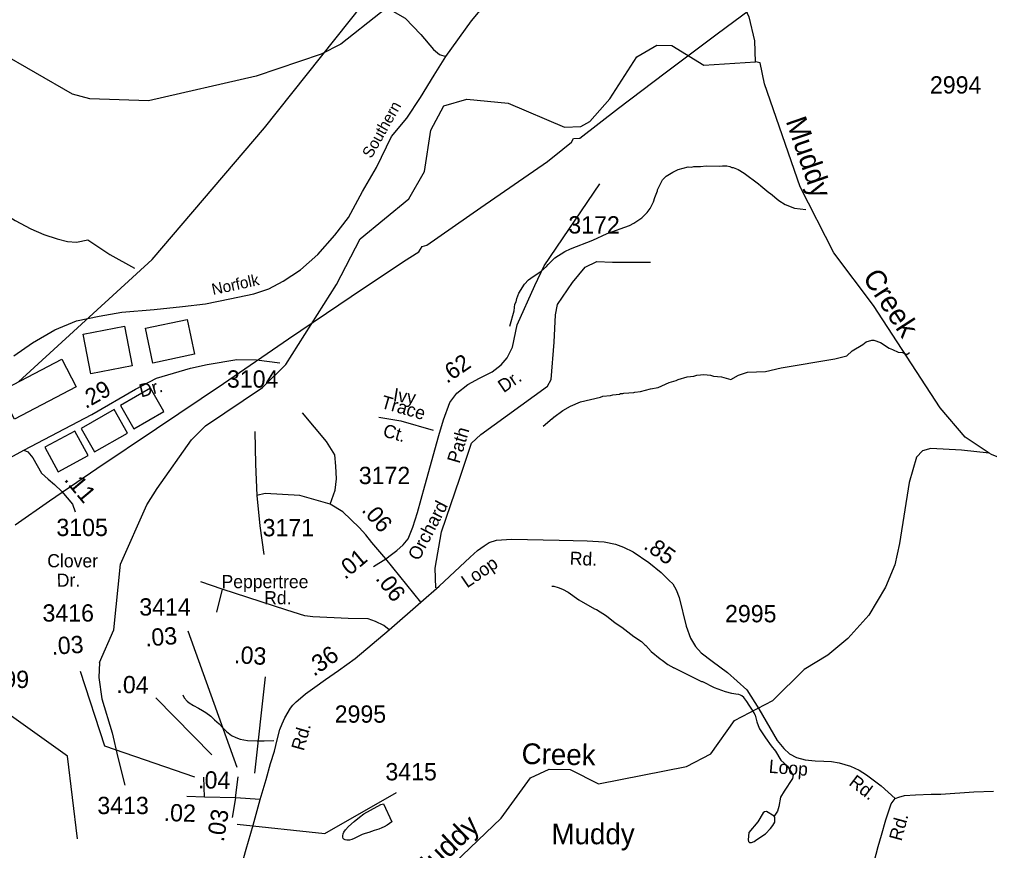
# Model space of a CAD drawing. Extents: x 1547597 to 1699558, y 810033 to 920809.
# Drawn here: x 1595166 to 1602180, y 820357 to 826362 of the extents above; entities that cross this region are included whole.
import ezdxf

# ---------------------------------------------------------------- set-up
doc = ezdxf.new("R2010")
doc.units = 0
for name, color, linetype in [('Exist Boundary Political City Limit New', 7, 'Continuous'), ('Exist Cultural Church with Cemetery Label', 7, 'Continuous'), ('Exist Cultural Warehouse Building Footprint', 7, 'Continuous'), ('Exist Hydrographic Creek Single Shore', 7, 'Continuous'), ('Exist Hydrographic Misc Water Feature', 7, 'Continuous'), ('Exist Railroad Mainline', 7, 'Continuous'), ('Exist Railroad Mainline Label', 7, 'Continuous'), ('Exist Road Non-System Type 51', 7, 'Continuous'), ('Exist Road Non-System Type 51 Label', 7, 'Continuous'), ('Exist Road Secondary Mileage Hundredths English Label', 7, 'Continuous'), ('Exist Road Secondary Type 51 Attributed', 7, 'Continuous'), ('Exist Road Secondary Type 51 Label', 7, 'Continuous'), ('Exist Road Secondary Type 51 Number Label', 7, 'Continuous'), ('Exist Utilities Electrical Transmission Line', 7, 'Continuous'), ('Map Preparation Boundary City Limit Buffer Line', 7, 'Continuous'), ('Old_Level_32', 7, 'Continuous')]:
    doc.layers.add(name, color=color, linetype=linetype)

msp = doc.modelspace()

# ---------------------------------------------------------------- linework, layer by layer
at = {"layer": 'Exist Boundary Political City Limit New'}
msp.add_lwpolyline([(1595159.9, 823742.9), (1596126.5, 824626.4), (1596938.9, 825577.9), (1598671.6, 827755.3), (1599119.8, 828312.6), (1599862.2, 829685.3), (1600674.7, 831289.2), (1600128.4, 831887.3), (1599217.9, 832804.7), (1599067.4, 833015.2), (1598754.8, 833517.5), (1598535.5, 834121.7), (1598377.2, 834572.6), (1598149, 835207), (1597793.5, 835631), (1597451.9, 835864.5), (1596684.8, 836157), (1596268.5, 836512.2)], dxfattribs=at)
at = {"layer": 'Exist Cultural Warehouse Building Footprint'}
for points in [[(1595981.8, 823858.6), (1595682.6, 823800.3), (1595626.8, 824086.9), (1595926, 824145.1)], [(1596433.1, 823943), (1596131, 823879.6), (1596078.2, 824131.8), (1596380.2, 824195.2)], [(1595577.9, 823708.2), (1595130.7, 823474.8), (1595026.3, 823674.8), (1595473.5, 823908.2)], [(1596114.2, 823697.9), (1595896.6, 823573.4), (1595993.1, 823404.7), (1596210.7, 823529.1)], [(1595852.2, 823542.8), (1595612.8, 823407.2), (1595708.5, 823238.3), (1595947.9, 823374)], [(1595567.7, 823387.7), (1595351.3, 823270.9), (1595446.5, 823094.5), (1595662.9, 823211.4)]]:
    msp.add_lwpolyline(points, close=True, dxfattribs=at)
at = {"layer": 'Exist Hydrographic Creek Single Shore'}
for points in [[(1599148.6, 827468.1), (1599130.7, 827383.1), (1598893.6, 827085.9), (1598450.6, 827019.4), (1598373, 826911), (1597968.6, 826558.9), (1597775.8, 826410), (1597490.3, 826184.3), (1597347.3, 826111.7), (1596877.3, 825951.8), (1596099.6, 825773.7), (1595674.6, 825788.9), (1595550.7, 825820.9), (1595012.6, 826130.5), (1594738.6, 826218.2), (1594623.6, 826351.8), (1594518.6, 826587), (1594430.6, 826880.9), (1594384.6, 827203.6), (1594403.6, 827380.4), (1594498.6, 827654.3), (1594492.6, 827828.4), (1594348.6, 828264.6)], [(1600488.6, 826055.7), (1600482.7, 826206.8), (1600442.6, 826381.6), (1600353.6, 826550.8), (1600172.6, 826761.3), (1599545.6, 827253.3), (1599373.6, 827457), (1599331.6, 827474.3)], [(1595746.6, 821716.9), (1595849.6, 821951.2), (1595897.6, 822426.2), (1596086.7, 822855.7), (1596162.6, 822972.3), (1596409.6, 823325.1), (1596510.6, 823424.8), (1596922.7, 823702.1), (1597091.6, 823869.3), (1597457.6, 824446.2), (1597628.7, 824777.6), (1597982.6, 825065.9), (1598093.6, 825263.8), (1598139.6, 825561.6), (1598233.7, 825737), (1598401.6, 825786.1), (1598700.7, 825757), (1599106.7, 825584.7), (1599223.7, 825589), (1599290.6, 825623.7), (1599434.6, 825788.2), (1599630.7, 826092.8), (1599773.6, 826175.2), (1599881.7, 826173), (1600113.7, 826030.5), (1600488.6, 826055.7)], [(1602177, 823228.8), (1602003.6, 823343.1), (1601822.7, 823556.8), (1601340.6, 824295.3), (1601053.6, 824675.3), (1600810.7, 825153), (1600553.6, 825896.8), (1600521.6, 826048.5), (1600488.6, 826055.7)], [(1602177, 823228.8), (1601976.8, 823249.3), (1601755.2, 823260.9), (1601695.1, 823245.9), (1601652.4, 823198.6), (1601597.5, 823017.2), (1601528.2, 822576), (1601493.7, 822420.3), (1601427.1, 822259.3), (1601307.9, 822059), (1601155.2, 821889.4), (1601009.6, 821769.7), (1600839.8, 821665)], [(1603082.6, 822996.2), (1602433.6, 823120.9), (1602193.6, 823217.8), (1602177, 823228.8)], [(1595746.6, 821716.9), (1595740.5, 821606.9), (1595763.4, 821453.1), (1595837.8, 821207.4), (1595878.8, 821030.6), (1595929.5, 820829.6)], [(1597762.7, 819736), (1597806.6, 819853.3), (1597907.6, 819959.6), (1598142.6, 820105.9), (1598649.6, 820591.2), (1598861.6, 820882.3), (1598995.6, 820945.3), (1599146.7, 820942.2), (1599353.7, 820839.6), (1599988.6, 820964.6), (1600164.6, 821056.2), (1600334.6, 821295.7), (1600611.6, 821441.1), (1600839.8, 821665)]]:
    msp.add_lwpolyline(points, dxfattribs=at)
at = {"layer": 'Exist Hydrographic Misc Water Feature'}
for points in [[(1598712.7, 824146.2), (1598742.2, 824257.7), (1598748.9, 824305.6), (1598757.1, 824321.5), (1598761.4, 824345.4), (1598775.9, 824383.2), (1598818.8, 824448.6), (1598847.2, 824480.2), (1598879.5, 824505.7), (1598936, 824540.9), (1598976.5, 824576.4), (1598988.7, 824592.2), (1599037.3, 824639.5), (1599109.8, 824684.5), (1599150, 824703.9), (1599310.8, 824767.7), (1599415.5, 824816.2), (1599576.1, 824873.9), (1599608.3, 824889.5), (1599664.8, 824928.7), (1599703.4, 824968.2), (1599725.7, 824995.8), (1599750.3, 825043.5), (1599758.7, 825075.3), (1599779.4, 825123), (1599779.5, 825131), (1599814.5, 825202.5), (1599840.9, 825230.2), (1599889.1, 825259.5), (1599929.4, 825278.9), (1600001.6, 825295.9), (1600025.6, 825295.6), (1600041.6, 825299.4), (1600089.6, 825298.7), (1600129.7, 825304.1), (1600225.5, 825300.8), (1600249.6, 825304.4), (1600279.6, 825304), (1600301.5, 825299.7), (1600317.4, 825291.5), (1600325.4, 825291.4), (1600361.2, 825276.9), (1600404.8, 825252.3), (1600509.6, 825174.8), (1600525.4, 825158.6), (1600582.7, 825111.8), (1600596.7, 825103.6), (1600655.9, 825052.8), (1600701.6, 825024.2), (1600769.1, 824997.3), (1600851, 824987.8)], [(1601186.3, 823968.7), (1601263.4, 824014.6), (1601287.6, 824032.3), (1601327.8, 824045.7), (1601343.8, 824045.5), (1601391.6, 824028.8), (1601454.9, 823986), (1601478.8, 823977.6), (1601518.5, 823957.1), (1601550.4, 823954.6), (1601582.3, 823942.2), (1601599.7, 823954.9)], [(1600241.5, 823780.5), (1600310.2, 823760.6), (1600363.9, 823791.3), (1600429.9, 823812.5), (1600559, 823819.5), (1600672.7, 823843.8), (1601061.9, 823910.3), (1601147.2, 823932.1), (1601186.3, 823968.7)], [(1598952.7, 823423), (1599017.4, 823478), (1599023.4, 823479.9), (1599029.6, 823487.9), (1599094.2, 823536.9), (1599150.6, 823568.2), (1599222.9, 823599.2), (1599367.3, 823633.1), (1599383.4, 823640.9), (1599439.5, 823644.1), (1599455.5, 823649.9), (1599503.5, 823655.2), (1599511.5, 823659.1), (1599527.5, 823658.9), (1599535.6, 823662.8), (1599607.6, 823665.8), (1599615.7, 823669.7), (1599655.7, 823673.1), (1599728, 823694.1), (1599784.1, 823703.3), (1599864.4, 823738.2), (1599913, 823753.6), (1599928.7, 823761.3), (1599993, 823780.4), (1600041, 823783.7), (1600063, 823791.4), (1600089.1, 823795.1), (1600113.1, 823796.7), (1600161, 823792), (1600184.9, 823785.7), (1600241.5, 823780.5)], [(1599015.5, 822266.3), (1599028.9, 822266.2), (1599060.7, 822257.7), (1599092.5, 822245.3), (1599132.3, 822224.7), (1599211.5, 822167.7), (1599322.5, 822104.1), (1599338.4, 822097.9), (1599409.7, 822052.9), (1599473, 822002), (1599520.6, 821971.4), (1599607.6, 821904.2), (1599663.1, 821867.4), (1599686.8, 821843.1), (1599694.7, 821839), (1599732.1, 821796.5), (1599797.3, 821741.6), (1599813.2, 821733.4), (1599852.6, 821700.8), (1599897.7, 821677.5)], [(1600484.2, 821336), (1600476.9, 821351.8), (1600461.9, 821378.1), (1600441, 821408.6), (1600423.9, 821434.9), (1600402.8, 821463.4), (1600389.2, 821475.7), (1600379.4, 821479.9), (1600367.5, 821484.1), (1600345.4, 821488), (1600315.8, 821491.8), (1600271.6, 821502.8), (1600244.1, 821513.4), (1600190.1, 821533.8), (1600107, 821575.3), (1600099.3, 821575.5), (1599897.7, 821677.5)], [(1600484.2, 821336), (1600490.1, 821315.4), (1600498.2, 821287.2), (1600506.5, 821260), (1600517.3, 821236.2), (1600560.4, 821171.5), (1600601.4, 821114.8), (1600632.8, 821074.3), (1600671.6, 821009.7), (1600717.7, 820966), (1600754.9, 820907.2), (1600759.9, 820904.2), (1600755.2, 820877.2), (1600694.2, 820787.2), (1600667.2, 820744), (1600656, 820674.3), (1600647.5, 820642.4), (1600622.5, 820606.5)], [(1597798.2, 820694.6), (1597858.4, 820563.9), (1597842.5, 820552), (1597824.2, 820540.6), (1597802.6, 820528.7), (1597786.9, 820520.8), (1597765.4, 820512.5), (1597731.8, 820502.3), (1597691.5, 820488.7), (1597666.1, 820479.9), (1597645.2, 820473.1), (1597619.1, 820461.3), (1597587.4, 820445), (1597568.6, 820436.7), (1597551.8, 820432.4), (1597534.5, 820432.6), (1597520.4, 820434.8), (1597511.8, 820439), (1597507.3, 820445.1), (1597504.4, 820452.8), (1597504.5, 820462.9), (1597507.3, 820477.6), (1597512, 820489.2), (1597523.4, 820505.8), (1597545, 820530.3), (1597585.5, 820566.3), (1597625, 820599.2), (1597656.7, 820622), (1597704.3, 820649.2), (1597779.9, 820688.8), (1597798.2, 820694.6)], [(1600622.5, 820606.5), (1600567.5, 820639.9), (1600551.5, 820636.2), (1600543.4, 820630.3), (1600504.2, 820565.1), (1600439, 820486.6), (1600434.9, 820433.9), (1600437.7, 820422.3), (1600443.3, 820416.3), (1600458, 820416.1), (1600477, 820423), (1600496.2, 820437.2), (1600560.8, 820478.1), (1600595.4, 820515.5), (1600613.8, 820539.1), (1600626.2, 820562.9), (1600626.7, 820594.9), (1600620.9, 820603), (1600622.5, 820606.5)]]:
    msp.add_lwpolyline(points, dxfattribs=at)
at = {"layer": 'Exist Railroad Mainline'}
for points in [[(1598248, 826093.7), (1598434.5, 826352.6), (1598624.1, 826581.4)], [(1595125.4, 823932.3), (1595260.4, 824026.6), (1595423.5, 824120.5), (1595580.1, 824184.4), (1595742.3, 824218.3), (1595906.6, 824248.2), (1596140.5, 824267.3), (1596344.4, 824288.8), (1596512.5, 824306.6), (1596688.7, 824342.2), (1596861.2, 824380.1), (1596969.4, 824416.8), (1597071.9, 824471.3), (1597198.9, 824553.8), (1597324.2, 824664.1), (1597445.9, 824802.5), (1597545.3, 824931.2), (1597645.8, 825119.8), (1597747.7, 825292.3), (1597856.6, 825516.8), (1597967, 825648), (1598064.7, 825798.7), (1598163.8, 825958.2), (1598248, 826093.7)]]:
    msp.add_lwpolyline(points, dxfattribs=at)
at = {"layer": 'Exist Road Non-System Type 51'}
for q in [(1596477.8, 822297.5), (1596592, 822078.8)]:
    msp.add_line((1596633.3, 822246.5), q, dxfattribs=at)
for points in [[(1596624.4, 827610.7), (1596699.4, 827543.8), (1596786.8, 827483.8), (1596868, 827402.5), (1596886.1, 827357.3), (1596889.1, 827279), (1596862, 827146.6), (1596843.2, 827072.2), (1596868, 826996), (1596961.3, 826899.7), (1597165.9, 826791.3), (1597328.3, 826701), (1597454.7, 826631.7), (1597649.4, 826536.3), (1597775.7, 826473), (1597956.2, 826370.7), (1598067.5, 826253.3), (1598159, 826144.6), (1598202.5, 826108.1), (1598248, 826093.7)], [(1594476.3, 824699.7), (1594535.6, 824749.1), (1594616.2, 824816.1), (1594717.3, 824894.7), (1594816, 824969.3), (1594874.5, 825008.6), (1594892.8, 825015.6), (1594912.7, 825020.2), (1594929.9, 825021), (1594946.5, 825019.7), (1594961.3, 825017.8), (1594974.4, 825013.9), (1594996.4, 825001.7), (1595039.8, 824970.6), (1595137, 824909.4), (1595250, 824849.9), (1595343.5, 824808.7), (1595438.9, 824777.6), (1595514.5, 824758.6), (1595578.3, 824753.8), (1595660.4, 824768.7)], [(1595660.4, 824768.7), (1595821, 824664.8), (1595999.5, 824564.5)], [(1598177.3, 822256.4), (1598172.7, 822398.5), (1598218.5, 822659.7), (1598351, 823047.5), (1598433.5, 823299.6), (1598502.1, 823363.8), (1598982.9, 823712.1), (1599009.9, 823760.8), (1599032.8, 824031.1), (1599042, 824228.2), (1599055.7, 824301.5), (1599165.6, 824461.9), (1599257.2, 824571.9), (1599339.6, 824613.2), (1599454, 824608.6), (1599728.2, 824607.5)], [(1596524.4, 823869.3), (1596737.2, 823904), (1596880.9, 823903.1), (1597049.7, 823880.9)], [(1597413.5, 822859), (1597450.1, 822959.8), (1597459.3, 823042.3), (1597454.7, 823133.9), (1597445.5, 823216.4), (1597386, 823312.7), (1597212, 823518.9)], [(1597764.3, 823488), (1597923, 823462.4), (1598156.9, 823394.9)], [(1596868.6, 823386), (1596873.2, 823147.7), (1596882.3, 822923.1)], [(1597413.5, 822859), (1597193.7, 822923.1), (1596941.9, 822936.9), (1596882.3, 822923.1)], [(1596882.3, 822923.1), (1596905.2, 822703.1), (1596932.7, 822496.9)], [(1597622.6, 822690.1), (1597505, 822804), (1597413.5, 822859)], [(1597839.3, 821952), (1597799.7, 821984), (1597741.4, 822013.2), (1597687.9, 822030.2), (1597542.1, 822032.6), (1597287, 822044.8), (1597228.6, 822052.1), (1597099.9, 822093.4), (1596633.3, 822246.5)], [(1596349, 821482.8), (1596356.8, 821460.8), (1596380.3, 821435.3), (1596394.5, 821424.6), (1596424.1, 821406), (1596461.9, 821385.6), (1596489.6, 821369.3), (1596513.7, 821353.8), (1596549.2, 821328.6), (1596576.9, 821302.3), (1596610.5, 821272), (1596638.1, 821243.6), (1596663.8, 821217.3), (1596699.5, 821188.9), (1596731.4, 821174.5), (1596761.1, 821162.3), (1596815.2, 821151.6), (1596885.1, 821148.7), (1596935, 821150.1), (1597004.9, 821152.3)]]:
    msp.add_lwpolyline(points, dxfattribs=at)
at = {"layer": 'Exist Road Secondary Mileage Hundredths English Label'}
for p, q in [((1596867.8, 820917.3), (1596945.5, 821612.2)), ((1596556.7, 821048.5), (1596153.4, 821461.6))]:
    msp.add_line(p, q, dxfattribs=at)
msp.add_lwpolyline([(1595585.9, 820441), (1595514.3, 821038.8), (1595023.4, 821388.7)], dxfattribs=at)
at = {"layer": 'Exist Road Secondary Type 51 Attributed'}
for p, q in [((1597726.2, 822408.3), (1597815.2, 822465.3)), ((1598067.5, 822152.3), (1597815.2, 822465.3)), ((1596503.9, 820743.5), (1596500.2, 820886.9)), ((1596727.5, 820737.4), (1596748.1, 820890.5)), ((1596503.9, 820743.5), (1596377.5, 820747.1)), ((1596727.5, 820737.4), (1596503.9, 820743.5)), ((1596727.5, 820737.4), (1596704.4, 820596.5)), ((1596907.5, 820726.1), (1596727.5, 820737.4))]:
    msp.add_line(p, q, dxfattribs=at)
for points in [[(1597815.2, 822465.3), (1597856.7, 822495.3), (1597894.5, 822525.3), (1597940.9, 822564.9), (1597977.6, 822610.3), (1598010.7, 822692.6), (1598044.7, 822799.3), (1598096.9, 822992.4), (1598199.1, 823355.7), (1598233.1, 823469.3), (1598278.5, 823594.4), (1598328.4, 823662.5), (1598407.9, 823723.9), (1598493.5, 823770.4), (1598584.2, 823815.8), (1598647.8, 823865.8), (1598693.2, 823918), (1598730.8, 823995.3), (1598765.1, 824156.4), (1598891.7, 824438.9), (1598960.3, 824581.5), (1599362, 825175)], [(1595197.7, 823249.3), (1595690.4, 823508.1), (1596006.7, 823691.5), (1596156.8, 823769), (1596404.1, 823842.6), (1596524.4, 823869.3)], [(1594303.8, 822760.2), (1595197.7, 823249.3)], [(1595197.7, 823249.3), (1595228.2, 823238.3), (1595263.5, 823194.7), (1595327.1, 823084.6), (1595374.2, 823040.3), (1595419.8, 823002.3), (1595472.4, 822952.5), (1595550.6, 822859), (1595568.6, 822804.4)], [(1597815.2, 822465.3), (1597713.4, 822583.3), (1597670.2, 822637.9), (1597622.6, 822690.1)], [(1598067.5, 822152.3), (1598200.7, 822266.6), (1598424.3, 822477.4), (1598479, 822526.1), (1598525.7, 822557.9), (1598562.5, 822583.7), (1598614.2, 822599.6), (1598724.6, 822607.6), (1599068.5, 822599.6), (1599270.3, 822593.7), (1599392.6, 822586.7), (1599475.6, 822571.3), (1599533.3, 822550), (1599602.8, 822514.6), (1599716.2, 822438.4), (1599805.4, 822367), (1599862.8, 822309.4), (1599890.6, 822283.5), (1599913.5, 822240.8), (1599935.3, 822185.1), (1599986.5, 821978.8), (1600017.3, 821892.4), (1600054.6, 821832.2), (1600095.4, 821786.5), (1600174.9, 821724.9), (1600285.7, 821643.8), (1600425.3, 821518.9), (1600510.4, 821381.4), (1600644.1, 821152.4), (1600691.3, 821095.1), (1600733.1, 821055.4), (1600782.8, 821030.5), (1600846.4, 821011.6), (1600919.4, 821006.1), (1600981, 821002.7), (1601036.7, 821001.2), (1601092.4, 820991.2), (1601174.4, 820967.9), (1601238, 820937.1), (1601290.7, 820904.3), (1601395.8, 820824.2), (1601498, 820732.8)], [(1596907.5, 820726.1), (1596951.1, 820871), (1596981, 820987.3), (1597010.3, 821076.2), (1597029.2, 821157.7), (1597050, 821231.3), (1597065.5, 821273.5), (1597084.3, 821315.3), (1597127.1, 821384.9), (1597142.9, 821407.6), (1597166, 821430.7), (1597197.2, 821458.9), (1597234, 821489.8), (1597302.5, 821537.5), (1597379.9, 821593.9), (1597472.2, 821657.9), (1597594.3, 821744.7), (1597839.3, 821952), (1598067.5, 822152.3)], [(1601498, 820732.8), (1601524.8, 820743.7), (1601565, 820754.5), (1601645.1, 820759.6), (1601757.4, 820764.6), (1601828, 820764.6), (1602065.1, 820781), (1602207.3, 820786)], [(1596671.3, 819936), (1596726, 820083.2), (1596806.5, 820367.5), (1596855.7, 820540.9), (1596907.5, 820726.1)], [(1601040.5, 819208.9), (1601059.3, 819252.1), (1601093.9, 819347.4), (1601138.3, 819516.9), (1601190.5, 819712.6), (1601208.4, 819772.1), (1601232.1, 819863.8), (1601292.3, 820084.4), (1601330.5, 820219.2), (1601373.7, 820386.9), (1601398.1, 820468.9), (1601428.9, 820578.2), (1601467.2, 820694), (1601498, 820732.8)]]:
    msp.add_lwpolyline(points, dxfattribs=at)
at = {"layer": 'Exist Road Secondary Type 51 Number Label'}
msp.add_line((1596741.4, 820956.1), (1596386.6, 821942.7), dxfattribs=at)
for points in [[(1596435.2, 820888.1), (1595784, 821111.7), (1595609, 821651.1)], [(1596741.4, 820547.9), (1597373.2, 820479.8), (1597893.3, 820776.3)]]:
    msp.add_lwpolyline(points, dxfattribs=at)
at = {"layer": 'Exist Utilities Electrical Transmission Line'}
msp.add_lwpolyline([(1595134.6, 822711.6), (1595385, 822883.6), (1595726.6, 823118.2), (1596158.6, 823405.4), (1596641.3, 823731.8), (1597111.9, 824054.5), (1597564.4, 824361.3), (1597941.9, 824613.4), (1598055, 824683.5), (1598077.5, 824721.1), (1598111.7, 824730.6), (1598501.7, 825002.4), (1598984.3, 825336.8), (1599095.8, 825425), (1599158.4, 825474.2), (1599170.8, 825501.9), (1599218.8, 825503.2), (1599496, 825720.9), (1599833.7, 825975.4), (1600209.6, 826257.5), (1600626.2, 826568.8)], dxfattribs=at)
at = {"layer": 'Map Preparation Boundary City Limit Buffer Line'}
msp.add_lwpolyline([(1595159.9, 823742.9), (1596126.5, 824626.4), (1596938.9, 825577.9), (1598671.6, 827755.3), (1599119.8, 828312.6), (1599862.2, 829685.3), (1600674.7, 831289.2), (1600128.4, 831887.3), (1599217.9, 832804.7), (1599067.4, 833015.2), (1598754.8, 833517.5), (1598535.5, 834121.7), (1598377.2, 834572.6), (1598149, 835207), (1597793.5, 835631), (1597451.9, 835864.5), (1596684.8, 836157), (1596268.5, 836512.2)], dxfattribs=at)

# ---------------------------------------------------------------- texts
at = {"layer": 'Exist Cultural Church with Cemetery Label'}
msp.add_text('Muddy ', height=150, dxfattribs=at).set_placement((1599012, 820402.6))
at = {"layer": 'Exist Railroad Mainline Label'}
for s, rotation, p in [('Southern', 60.53389, (1597710.8, 825353)), ('Norfolk', 12.25914, (1596566.2, 824370.2))]:
    msp.add_text(s, height=82.02, rotation=rotation, dxfattribs=at).set_placement(p)
at = {"layer": 'Exist Road Non-System Type 51 Label'}
for s, rotation, p in [('Trace', 343.90701, (1597773.4, 823556.8)), ('Ivy', 350.81586, (1597863.8, 823606.9)), ('Ct.', 343.90701, (1597787.6, 823351.3))]:
    msp.add_text(s, height=95, rotation=rotation, dxfattribs=at).set_placement(p)
at = {"layer": 'Exist Road Secondary Mileage Hundredths English Label'}
for s, height, rotation, p in [('.62', 120, 34.43721, (1598256.8, 823727.8)), ('.29', 120, 29.38071, (1595645.9, 823546.6)), ('.11', 125, 309.93058, (1595484.6, 823035.3)), ('.06', 120, 310.73587, (1597635.3, 822813.5)), ('.85', 120, 324.76565, (1599671.9, 822543.4)), ('.01', 120, 40.03026, (1597520.9, 822311)), ('.06', 120, 307.17588, (1597735.8, 822321)), ('.03', 125, 4.69678, (1596079.3, 821830.6)), ('.03', 125, 3.68228, (1595401.6, 821771.4)), ('.03', 125, 356.39783, (1596715.8, 821712.1)), ('.36', 125, 34.75115, (1597295.5, 821611.4)), ('.04', 125, 358.44343, (1595866.4, 821496.1)), ('.04', 125, 358.44343, (1596457, 820807.3)), ('.02', 125, 358.3477, (1596208, 820570.4)), ('.03', 125, 80.69795, (1596643.1, 820415.6))]:
    msp.add_text(s, height=height, rotation=rotation, dxfattribs=at).set_placement(p)
at = {"layer": 'Exist Road Secondary Type 51 Label'}
for s, rotation, p in [('Dr.', 34.43721, (1598666.8, 823661.2)), ('Dr.', 14.87027, (1596046.6, 823630.4)), ('Path', 73.69379, (1598347.5, 823148.7)), ('Orchard', 62.36102, (1598054, 822445)), ('Rd.', 357.44987, (1599143.1, 822422.6)), ('Clover', 359.83462, (1595367.7, 822403.8)), ('Loop', 34.4949, (1598402.5, 822250.6)), ('Dr.', 0.40831, (1595436.6, 822262.9)), ('Rd.', 74.20799, (1597221.4, 821072.4)), ('Loop', 355.24686, (1600581.1, 820919.6)), ('Rd.', 322.52327, (1601156.2, 820835.8)), ('Rd.', 74.82471, (1601542.6, 820420.7))]:
    msp.add_text(s, height=95, rotation=rotation, dxfattribs=at).set_placement(p)
for s, p in [('Peppertree', (1596627.4, 822252.8)), ('Rd.', (1596935.6, 822136.4))]:
    msp.add_text(s, height=95, dxfattribs=at).set_placement(p)
at = {"layer": 'Exist Road Secondary Type 51 Number Label'}
for s, p in [('2994', (1601748.5, 825826.7)), ('3172', (1599134.6, 824815.3)), ('3104', (1596666.7, 823701.6)), ('3172', (1597619.7, 823004.8)), ('3105', (1595433.9, 822629.5)), ('3171', (1596924.4, 822627.6)), ('3414', (1596033.3, 822055)), ('3416', (1595333.5, 822011.3)), ('2995', (1600267.3, 822006.2)), ('2999', (1594864.7, 821531.6)), ('2995', (1597445.6, 821280.9)), ('3415', (1597812.1, 820864.3)), ('3413', (1595729.9, 820620.5))]:
    msp.add_text(s, height=125, dxfattribs=at).set_placement(p)
at = {"layer": 'Old_Level_32'}
for s, rotation, p in [('Muddy', 289.06406, (1600704.6, 825628.8)), ('Creek', 303.13584, (1601257.3, 824498.9)), ('Creek', 358.83324, (1598795.3, 820982.8)), ('Muddy', 43.75116, (1598066.8, 820104.3))]:
    msp.add_text(s, height=150, rotation=rotation, dxfattribs=at).set_placement(p)

doc.saveas('drawing.dxf')
